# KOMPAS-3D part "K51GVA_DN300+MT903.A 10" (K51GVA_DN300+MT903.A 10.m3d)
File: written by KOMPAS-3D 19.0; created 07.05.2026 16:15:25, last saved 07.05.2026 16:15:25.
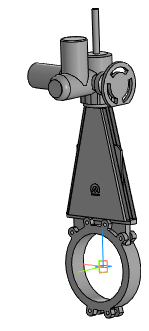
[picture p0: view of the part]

Document properties: Автор: Энергия; Полное имя файла: ..\K51GVA_DN50-DN1000+MT903.A\K51GVA_DN300+MT903.A 10.a3d

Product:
- Part/product: K51GVA_DN300+MT903.A 10
    Масса: 121.83

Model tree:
1. Операция без истории:1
